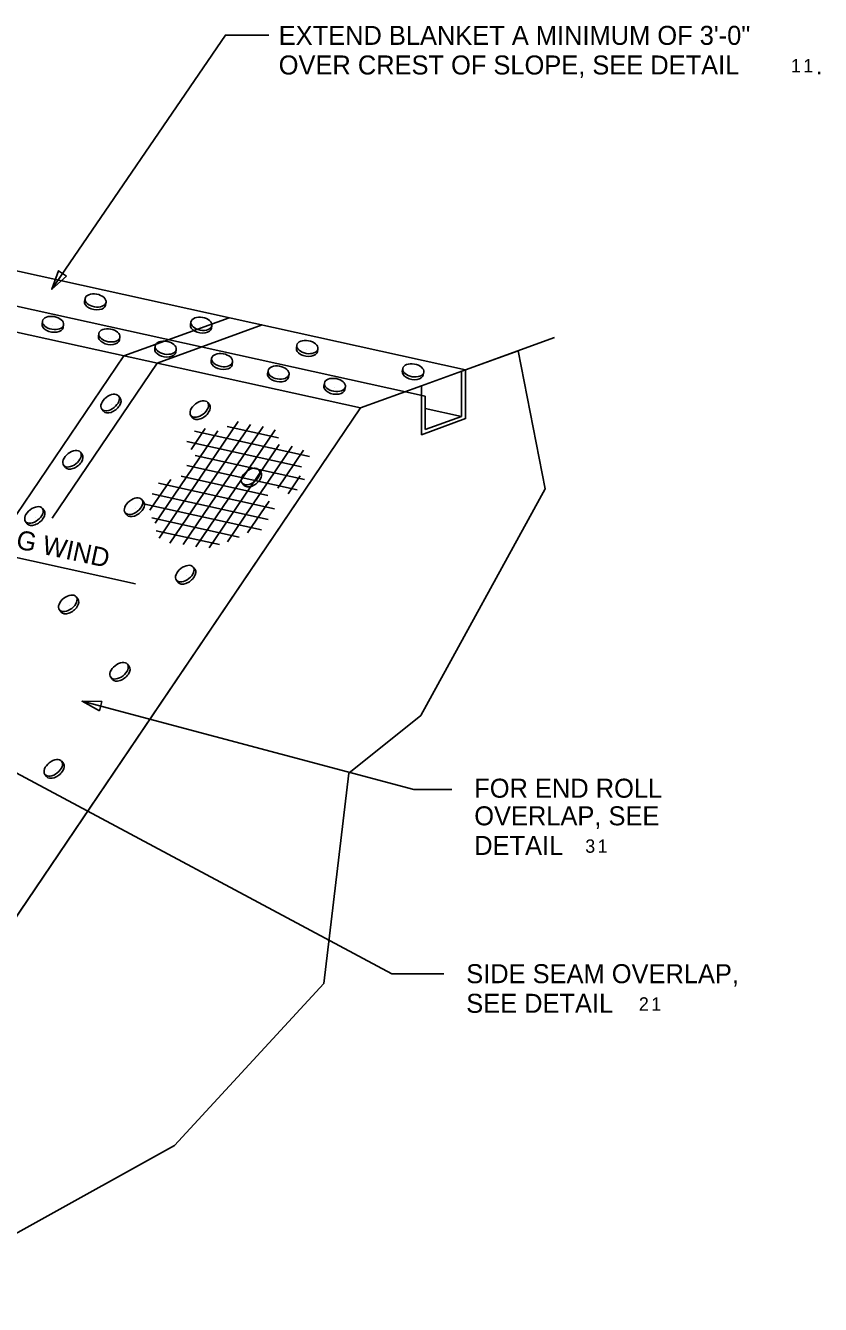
# Model space of a CAD drawing. Extents: x 27123946 to 27124151, y 1145898 to 1146027.
# Drawn here: x 27123989.4 to 27124024, y 1145962.9 to 1146018.6 of the extents above; entities that cross this region are included whole.
import ezdxf

# ---------------------------------------------------------------- set-up
doc = ezdxf.new("R2010")
doc.units = 0
for name, color, linetype in [('C-EROS', 7, 'Continuous'), ('C-PVMT', 7, 'Continuous'), ('Default', 7, 'Continuous'), ('G-ANNO-TEXT', 7, 'Continuous'), ('L-SITE-SOIL', 7, 'Continuous')]:
    doc.layers.add(name, color=color, linetype=linetype)

# ---------------------------------------------------------------- blocks, each defined once
blk = doc.blocks.new('mesh')
at = {"layer": 'Default'}
for p, q in [((0.00571, 0.03821), (-0.03747, -0.02556)), ((0.01235, 0.03658), (-0.03165, -0.02839)), ((0.0193, 0.03543), (-0.02443, -0.02916)), ((-0.00042, 0.03553), (0.02772, 0.02934)), ((-0.00551, 0.03307), (-0.03971, -0.01743)), ((-0.01232, 0.03445), (-0.02009, 0.02298)), ((-0.01822, 0.03288), (0.04472, 0.01904)), ((0.02591, 0.03375), (-0.01747, -0.03032)), ((-0.02236, 0.02723), (0.04043, 0.01343)), ((0.02814, 0.02562), (-0.01014, -0.03092)), ((0.03527, 0.02472), (-0.00015, -0.02758)), ((0.0415, 0.0225), (0.02744, 0.00172)), ((-0.02245, 0.01413), (0.038, 0.00084)), ((-0.0178, 0.01967), (0.04195, 0.00653)), ((-0.0256, 0.00826), (0.02188, -0.00218)), ((0.03971, 0.00843), (0.03309, -0.00136)), ((-0.03125, 0.00649), (-0.0426, -0.01028)), ((-0.03797, 0.00442), (0.0256, -0.00956)), ((-0.04137, -0.00139), (0.02214, -0.01536)), ((0.02264, -0.00537), (0.01084, -0.02279)), ((-0.04533, -0.00708), (0.01838, -0.02109)), ((-0.04159, -0.01447), (0.0063, -0.025)), ((-0.03929, -0.02154), (-0.00457, -0.02917))]:
    blk.add_line(p, q, dxfattribs=at)

msp = doc.modelspace()

# ---------------------------------------------------------------- linework, layer by layer
at = {"layer": 'C-PVMT'}
for p, q in [((27123972.944, 1146011.45), (27124008.592, 1146003.611)), ((27123972.764, 1146009.952), (27124006.832, 1146002.461)), ((27123970.86, 1146009.24), (27124004.016, 1146001.949)), ((27123991.995, 1146006.587), (27123992.016, 1146006.707)), ((27123992.452, 1146006.507), (27123992.452, 1146006.507)), ((27123992.91, 1146006.426), (27123992.931, 1146006.545)), ((27123990.144, 1146005.609), (27123990.165, 1146005.728)), ((27123990.601, 1146005.528), (27123990.601, 1146005.528)), ((27123991.058, 1146005.447), (27123991.079, 1146005.567)), ((27123993.71, 1146004.215), (27123998.286, 1146005.877)), ((27123995.157, 1146003.897), (27123999.733, 1146005.559)), ((27123996.608, 1146005.573), (27123996.629, 1146005.692)), ((27123997.065, 1146005.492), (27123997.065, 1146005.492)), ((27123997.522, 1146005.412), (27123997.543, 1146005.531)), ((27123992.599, 1146005.069), (27123992.62, 1146005.188)), ((27123993.056, 1146004.988), (27123993.056, 1146004.988)), ((27123993.513, 1146004.908), (27123993.534, 1146005.027)), ((27124008.592, 1146003.611), (27124012.455, 1146005.015)), ((27123995.054, 1146004.529), (27123995.075, 1146004.648)), ((27123995.511, 1146004.448), (27123995.511, 1146004.448)), ((27123995.968, 1146004.368), (27123995.989, 1146004.487)), ((27124001.22, 1146004.559), (27124001.241, 1146004.678)), ((27124001.677, 1146004.478), (27124001.677, 1146004.478)), ((27124002.135, 1146004.397), (27124002.156, 1146004.517)), ((27123993.71, 1146004.215), (27123989.032, 1145997.305)), ((27123995.157, 1146003.897), (27123990.588, 1145997.148)), ((27123997.509, 1146003.989), (27123997.53, 1146004.108)), ((27123997.966, 1146003.908), (27123997.966, 1146003.908)), ((27123998.423, 1146003.828), (27123998.444, 1146003.947)), ((27123999.964, 1146003.449), (27123999.985, 1146003.569)), ((27124000.421, 1146003.369), (27124000.421, 1146003.369)), ((27124000.878, 1146003.288), (27124000.899, 1146003.407)), ((27124005.833, 1146003.544), (27124005.854, 1146003.664)), ((27124006.29, 1146003.464), (27124006.29, 1146003.464)), ((27124006.671, 1146002.913), (27124008.592, 1146003.611)), ((27124006.747, 1146003.383), (27124006.768, 1146003.503)), ((27124008.412, 1146003.546), (27124008.412, 1146001.576)), ((27124008.592, 1146003.611), (27124008.592, 1146001.48)), ((27124002.419, 1146002.909), (27124002.44, 1146003.029)), ((27124002.876, 1146002.829), (27124002.876, 1146002.829)), ((27124003.333, 1146002.748), (27124003.354, 1146002.868)), ((27124004.016, 1146001.949), (27124006.671, 1146002.913)), ((27124006.671, 1146002.913), (27124006.671, 1146000.782)), ((27123993.548, 1146002.373), (27123993.473, 1146002.468)), ((27123997.433, 1146002.09), (27123997.358, 1146002.185)), ((27124006.832, 1146002.461), (27124006.832, 1146001.002)), ((27124004.016, 1146001.949), (27123983.522, 1145971.68)), ((27123992.817, 1146001.8), (27123992.742, 1146001.896)), ((27123993.182, 1146002.087), (27123993.182, 1146002.087)), ((27123996.702, 1146001.517), (27123996.627, 1146001.613)), ((27123997.068, 1146001.804), (27123997.068, 1146001.804)), ((27124006.832, 1146001.924), (27124008.412, 1146001.576)), ((27124006.671, 1146000.782), (27124008.592, 1146001.48)), ((27124006.832, 1146001.002), (27124008.412, 1146001.576)), ((27123991.891, 1145999.926), (27123991.816, 1146000.021)), ((27123991.16, 1145999.353), (27123991.085, 1145999.449)), ((27123991.525, 1145999.64), (27123991.525, 1145999.64)), ((27123999.301, 1145998.867), (27123999.301, 1145998.867)), ((27123999.666, 1145999.153), (27123999.591, 1145999.249)), ((27123998.935, 1145998.581), (27123998.86, 1145998.676)), ((27123994.569, 1145997.86), (27123994.494, 1145997.956)), ((27123989.868, 1145997.192), (27123989.868, 1145997.192)), ((27123990.234, 1145997.479), (27123990.159, 1145997.574)), ((27123993.838, 1145997.288), (27123993.764, 1145997.383)), ((27123994.204, 1145997.574), (27123994.204, 1145997.574)), ((27123989.503, 1145996.906), (27123989.428, 1145997.001)), ((27123996.802, 1145994.924), (27123996.727, 1145995.019)), ((27123996.071, 1145994.351), (27123995.997, 1145994.446)), ((27123996.437, 1145994.637), (27123996.437, 1145994.637)), ((27123991.34, 1145993.344), (27123991.34, 1145993.344)), ((27123991.705, 1145993.631), (27123991.631, 1145993.726)), ((27123990.975, 1145993.058), (27123990.9, 1145993.154)), ((27123993.938, 1145990.694), (27123993.864, 1145990.79)), ((27123993.208, 1145990.122), (27123993.133, 1145990.217)), ((27123993.573, 1145990.408), (27123993.573, 1145990.408)), ((27123991.075, 1145986.465), (27123991, 1145986.56)), ((27123990.709, 1145986.178), (27123990.709, 1145986.178)), ((27123990.344, 1145985.892), (27123990.269, 1145985.987))]:
    msp.add_line(p, q, dxfattribs=at)
for centre, major_axis in [((27123992.473, 1146006.626), (-0.457, 0.081)), ((27123990.622, 1146005.647), (-0.457, 0.081)), ((27123997.086, 1146005.612), (-0.457, 0.081)), ((27123993.077, 1146005.107), (-0.457, 0.081)), ((27123995.532, 1146004.568), (-0.457, 0.081)), ((27124001.698, 1146004.597), (-0.457, 0.081)), ((27123997.987, 1146004.028), (-0.457, 0.081)), ((27124006.311, 1146003.583), (-0.457, 0.081)), ((27124000.442, 1146003.488), (-0.457, 0.081)), ((27124002.897, 1146002.948), (-0.457, 0.081)), ((27123993.107, 1146002.182), (-0.365, -0.286)), ((27123996.993, 1146001.899), (-0.365, -0.286)), ((27123991.45, 1145999.735), (-0.365, -0.286)), ((27123999.226, 1145998.962), (-0.365, -0.286)), ((27123989.793, 1145997.288), (-0.365, -0.286)), ((27123994.129, 1145997.669), (-0.365, -0.286)), ((27123996.362, 1145994.733), (-0.365, -0.286)), ((27123991.265, 1145993.44), (-0.365, -0.286)), ((27123993.498, 1145990.503), (-0.365, -0.286)), ((27123990.634, 1145986.274), (-0.365, -0.286))]:
    msp.add_ellipse(centre, major_axis=major_axis, ratio=0.604498, dxfattribs=at)
for centre, major_axis in [((27123992.452, 1146006.507), (-0.457, 0.081)), ((27123990.601, 1146005.528), (-0.457, 0.081)), ((27123997.065, 1146005.492), (-0.457, 0.081)), ((27123993.056, 1146004.988), (-0.457, 0.081)), ((27123995.511, 1146004.448), (-0.457, 0.081)), ((27124001.677, 1146004.478), (-0.457, 0.081)), ((27123997.966, 1146003.908), (-0.457, 0.081)), ((27124000.421, 1146003.369), (-0.457, 0.081)), ((27124006.29, 1146003.464), (-0.457, 0.081)), ((27124002.876, 1146002.829), (-0.457, 0.081)), ((27123993.182, 1146002.087), (-0.365, -0.286)), ((27123997.068, 1146001.804), (-0.365, -0.286)), ((27123991.525, 1145999.64), (-0.365, -0.286)), ((27123999.301, 1145998.867), (-0.365, -0.286)), ((27123994.204, 1145997.574), (-0.365, -0.286)), ((27123989.868, 1145997.192), (-0.365, -0.286)), ((27123996.437, 1145994.637), (-0.365, -0.286)), ((27123991.34, 1145993.344), (-0.365, -0.286)), ((27123993.573, 1145990.408), (-0.365, -0.286)), ((27123990.709, 1145986.178), (-0.365, -0.286))]:
    msp.add_ellipse(centre, major_axis=major_axis, ratio=0.604498, start_param=0, end_param=3.141593, dxfattribs=at)
at = {"layer": 'G-ANNO-TEXT'}
for p, q in [((27123980.899, 1145997.218), (27123994.22, 1145994.289)), ((27123991.889, 1145989.175), (27124006.341, 1145985.331)), ((27123984.027, 1145988.731), (27124005.37, 1145977.306)), ((27124006.341, 1145985.331), (27124007.988, 1145985.331)), ((27124005.37, 1145977.306), (27124007.64, 1145977.306))]:
    msp.add_line(p, q, dxfattribs=at)
msp.add_lwpolyline([(27124000.022, 1146018.18), (27123998.13, 1146018.18), (27123990.57, 1146007.118)], dxfattribs=at)
for points in [[(27123991.212, 1146007.689), (27123990.57, 1146007.118), (27123990.868, 1146007.924)], [(27123992.641, 1145988.759), (27123991.889, 1145989.175), (27123992.748, 1145989.162)]]:
    msp.add_lwpolyline(points, close=True, dxfattribs=at)
at = {"layer": 'L-SITE-SOIL'}
msp.add_lwpolyline([(27123988.116, 1145978.465), (27124004.016, 1146001.949), (27124006.671, 1146002.913), (27124006.671, 1146000.782), (27124008.592, 1146001.48), (27124008.592, 1146003.611), (27124010.872, 1146004.439), (27124012.056, 1145998.427), (27124006.647, 1145988.554), (27124003.511, 1145986.047), (27124002.414, 1145976.879), (27123995.907, 1145969.827), (27123983.428, 1145962.909), (27123973.786, 1145963.536), (27123967.914, 1145964.234), (27123966.459, 1145964.755), (27123981.152, 1145970.093), (27123981.152, 1145967.64), (27123983.522, 1145968.501), (27123983.522, 1145971.083), (27123988.129, 1145977.887)], close=True, dxfattribs=at)

# ---------------------------------------------------------------- block references
at = {"layer": 'C-EROS', "xscale": 79.55254830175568, "yscale": 79.55254830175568}
msp.add_blockref('mesh', (27123998.233, 1145998.314), dxfattribs=at)

# ---------------------------------------------------------------- texts
at = {"layer": 'G-ANNO-TEXT'}
for s, height, p in [('EXTEND BLANKET A MINIMUM OF 3\'-0"', 0.828, (27124000.451, 1146017.757)), ('OVER CREST OF SLOPE, SEE DETAIL ', 0.828, (27124000.451, 1146016.467)), ('1', 0.58, (27124022.756, 1146016.562)), ('1', 0.58, (27124023.295, 1146016.562)), ('.', 0.828, (27124023.834, 1146016.467)), ('FOR END ROLL', 0.828, (27124008.966, 1145984.974)), ('OVERLAP, SEE', 0.828, (27124008.966, 1145983.771)), ('DETAIL ', 0.828, (27124008.966, 1145982.481)), ('3', 0.58, (27124013.801, 1145982.576)), ('1', 0.58, (27124014.34, 1145982.576)), ('SIDE SEAM OVERLAP,', 0.828, (27124008.617, 1145976.897)), ('SEE DETAIL ', 0.828, (27124008.617, 1145975.607)), ('2', 0.58, (27124016.136, 1145975.702)), ('1', 0.58, (27124016.675, 1145975.702))]:
    msp.add_text(s, height=height, dxfattribs=at).set_placement(p)
msp.add_text('PREVAILING WIND', height=0.82569, rotation=347.9229, dxfattribs=at).set_placement((27123983.328, 1145997.05))

doc.saveas('drawing.dxf')
